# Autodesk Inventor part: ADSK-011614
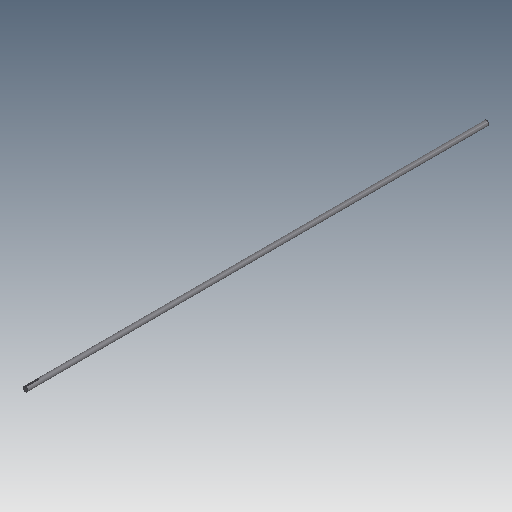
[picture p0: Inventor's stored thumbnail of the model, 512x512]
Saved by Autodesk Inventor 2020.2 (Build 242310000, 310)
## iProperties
Created: 1999-12
Part Number: ADSK-011614
Material: Acier doux
Description: SHFT-T,TH,FX,07-06,XX,ACME SHFT, HORIZONTAL BLANK ADJUST
Document SubType Name: Modeling
Designer: sspink
Density: 7.86 g/cm^3
Appearance: Metal-Steel(Polish)
Mass: 4063.64 g
Surface Area: 1094.99 cm^2
Volume: 517.003 cm^3
Control State: 0
Master: False
Checked Out: False
Shininess: 0.0
Length Units: 11272
Angle Units: 11279
Time Units: 11290
Mass Units: 11286
Length Display Precision: 3
Angle Display Precision: 2
Compacted: True
Cutlength: 71.5
Material Desc: THREADED-ROD,0.750-06ACME,RH
Material_Number: A084661
Dimensions: 0,7x71,5x0,8 in
Mass: 8,959 lb
VLT_Material: Acier doux
Density: 0.0
Volumn: 0.0
Area: 0.0
PropertySet Name: Model Information
Author: sspink
Revision Number: -
Title: SHFT-T,TH,FX,07-06,XX,ACME SHFT, HORIZONTAL BLANK ADJUST
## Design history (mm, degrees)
node "Extrusion1" dims "d1" = 1816.1, "d2" = 0
node "Extrusion3" dims "d12" = 50.8, "d13" = 0
node "Solide1"
node "Corps solides"
node "Corps surfaciques"
sketch "Sketch1"
  geometry: C1 r 9.525 at (27.54, -48.296)
  constraints: 1 centre point, 1 other
  dimensions: "d0" = 19.05 diameter of C1
sketch "Sketch5"
  geometry: L1 (0, 0)-(0, 6.833); L2 (0, 6.833)-(2.381, 6.833); L3 (2.381, 6.833)-(2.381, 9.223); L4 (0, 6.833)-(-2.381, 6.833); L5 (-2.381, 6.833)-(-2.381, 9.223); A1 r 9.525 centre (0, 0) between (2.381, 9.223) and (-2.381, 9.223) reference
  constraints: 10 end point, 4 perpendicular, 2 point on circle, 1 vertical
  dimensions: "d9" = 4.7625 distance between parallel lines of L3 L5; "d10" = 2.38125 distance between parallel lines of L1 L3; "d11" = 16.3576 dimension on A1 L2
